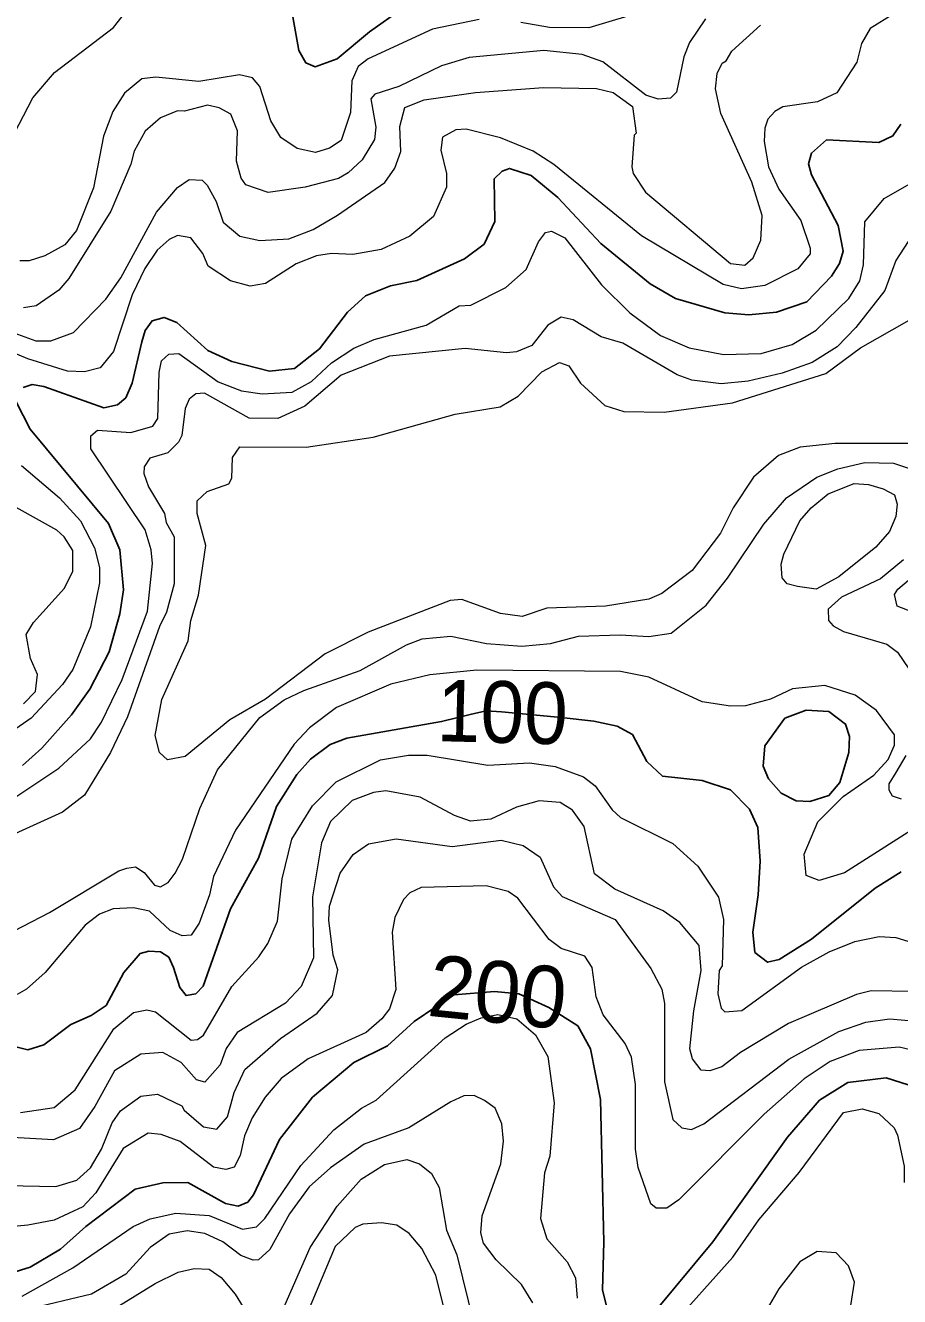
# Model space of a CAD drawing. Extents: x 673.6 to 698.9, y 7012 to 7040.1.
# Drawn here: x 696.817 to 697.951, y 7014.545 to 7016.194 of the extents above; entities that cross this region are included whole.
import ezdxf
from ezdxf.enums import TextEntityAlignment as Align

# ---------------------------------------------------------------- set-up
doc = ezdxf.new("R2010")
doc.units = 0
doc.header["$LTSCALE"] = 0.032
doc.layers.add('1', color=7, linetype='Continuous', lineweight=25)
doc.layers.add('2', color=7, linetype='Continuous', lineweight=13)
doc.layers.add('61', color=7, linetype='Continuous')

msp = doc.modelspace()

# ---------------------------------------------------------------- linework, layer by layer
at = {"layer": '1'}
for points in [[(697.3059, 7016.2157), (697.2629, 7016.1858), (697.2209, 7016.1507), (697.1924, 7016.1402), (697.1805, 7016.1453), (697.1715, 7016.1616), (697.1635, 7016.2053)], [(697.9522, 7016.0661), (697.9418, 7016.0508), (697.9237, 7016.0421), (697.8556, 7016.0454), (697.8364, 7016.0283), (697.8324, 7016.0145), (697.8361, 7016), (697.8709, 7015.9345), (697.8773, 7015.9013), (697.8725, 7015.8852), (697.8624, 7015.8686), (697.8301, 7015.8353), (697.7908, 7015.822), (697.7552, 7015.8187), (697.7238, 7015.8213), (697.6597, 7015.8397), (697.6272, 7015.8587), (697.5629, 7015.9113), (697.5073, 7015.971), (697.4729, 7015.9994), (697.4445, 7016.0085), (697.4352, 7016.005), (697.4248, 7015.9952), (697.4255, 7015.9397), (697.4117, 7015.9102), (697.3864, 7015.8912), (697.3244, 7015.8633), (697.2904, 7015.8563), (697.2577, 7015.8431), (697.2343, 7015.8222), (697.1981, 7015.7746), (697.1657, 7015.7489), (697.1332, 7015.7457), (697.0845, 7015.7581), (697.0533, 7015.7723), (697.0132, 7015.8085), (696.9966, 7015.8152), (696.9811, 7015.8108), (696.9721, 7015.7982), (696.9677, 7015.7838), (696.9551, 7015.7299), (696.9471, 7015.711), (696.9362, 7015.7018), (696.9184, 7015.6979), (696.8405, 7015.7258), (696.8254, 7015.7282), (696.8137, 7015.7245)], [(696.8045, 7015.7058), (696.8229, 7015.6703), (696.9244, 7015.548), (696.939, 7015.5138), (696.9439, 7015.462), (696.9392, 7015.4308), (696.9255, 7015.3815), (696.9004, 7015.333), (696.8765, 7015.2997), (696.8382, 7015.2568), (696.813, 7015.2342)], [(696.7763, 7014.8761), (696.8198, 7014.8656), (696.8408, 7014.872), (696.8756, 7014.8981), (696.902, 7014.9099), (696.9214, 7014.9228), (696.9445, 7014.9656), (696.9654, 7014.9902), (696.9766, 7014.9932), (696.9919, 7014.9925), (697.0027, 7014.9858), (697.0088, 7014.9722), (697.017, 7014.9464), (697.025, 7014.9359), (697.0377, 7014.9381), (697.0473, 7014.9478), (697.0827, 7015.0484), (697.1189, 7015.1141), (697.1425, 7015.181), (697.1689, 7015.2226), (697.1864, 7015.2426), (697.2119, 7015.2615), (697.2336, 7015.2698), (697.3565, 7015.2912), (697.3937, 7015.3002), (697.4144, 7015.3049), (697.4344, 7015.3036), (697.5114, 7015.2963), (697.5539, 7015.2916), (697.5844, 7015.2852), (697.604, 7015.2743), (697.6228, 7015.2394), (697.643, 7015.2205), (697.6946, 7015.2147), (697.7314, 7015.2028), (697.7558, 7015.1777), (697.7668, 7015.1538), (697.7698, 7015.1102), (697.7673, 7015.0663), (697.7602, 7015.0179), (697.7627, 7014.9918), (697.7793, 7014.979), (697.7944, 7014.9826), (697.8361, 7015.009), (697.9189, 7015.0749), (697.9527, 7015.0961)], [(697.5727, 7014.5245), (697.5654, 7014.5542), (697.5669, 7014.6161), (697.5627, 7014.8009), (697.5495, 7014.8666), (697.5331, 7014.8966), (697.4956, 7014.9202), (697.4569, 7014.9381), (697.4253, 7014.9409), (697.3727, 7014.9366), (697.3489, 7014.921), (697.3209, 7014.9024), (697.2863, 7014.8706), (697.2428, 7014.8488), (697.1891, 7014.804), (697.1464, 7014.7491), (697.1126, 7014.6776), (697.1051, 7014.6679), (697.0927, 7014.6626), (697.0763, 7014.6663), (697.0273, 7014.6936), (696.9949, 7014.6928), (696.9591, 7014.6847), (696.8949, 7014.6364), (696.862, 7014.6068), (696.8227, 7014.5837), (696.7792, 7014.5704)], [(698.0445, 7014.4841), (698.0566, 7014.549), (698.055, 7014.5816), (698.0436, 7014.6145), (698.0207, 7014.6633), (697.9826, 7014.7939), (697.9619, 7014.8202), (697.9333, 7014.8293), (697.8833, 7014.8232), (697.8468, 7014.8001), (697.8051, 7014.752), (697.7085, 7014.6165), (697.6361, 7014.5296)]]:
    msp.add_lwpolyline(points, dxfattribs=at)
msp.add_lwpolyline([(697.8019, 7015.2957), (697.8295, 7015.3058), (697.8589, 7015.304), (697.8806, 7015.2878), (697.8857, 7015.2718), (697.8849, 7015.2512), (697.8732, 7015.2121), (697.8589, 7015.1953), (697.8342, 7015.1873), (697.8165, 7015.1883), (697.797, 7015.1983), (697.7804, 7015.2167), (697.7738, 7015.2331), (697.7756, 7015.2595)], close=True, dxfattribs=at)
at = {"layer": '2'}
for points in [[(696.7967, 7016.0427), (696.8264, 7016.1), (696.8546, 7016.1327), (696.9311, 7016.1912), (696.9536, 7016.2198)], [(697.9432, 7016.209), (697.9126, 7016.19), (697.9012, 7016.1707), (697.8953, 7016.1462), (697.8691, 7016.1064), (697.844, 7016.095), (697.7993, 7016.0884), (697.7888, 7016.0824), (697.7798, 7016.0723), (697.7756, 7016.0606), (697.7748, 7016.0435), (697.7806, 7016.0105), (697.7938, 7015.9818), (697.8225, 7015.941), (697.8347, 7015.9049), (697.8344, 7015.8979), (697.8185, 7015.8783), (697.7759, 7015.8565), (697.7457, 7015.8524), (697.7218, 7015.858), (697.6156, 7015.9212), (697.5019, 7016.0134), (697.4753, 7016.0309), (697.4331, 7016.0481), (697.3885, 7016.0593), (697.3751, 7016.0587), (697.3578, 7016.0489), (697.3557, 7016.0323), (697.363, 7016.0019), (697.363, 7015.9842), (697.346, 7015.9463), (697.3153, 7015.9206), (697.2781, 7015.9032), (697.2414, 7015.8968), (697.2135, 7015.8983), (697.1942, 7015.8952), (697.1678, 7015.8846), (697.1283, 7015.8591), (697.1082, 7015.8556), (697.0827, 7015.8628), (697.0539, 7015.8818), (697.0469, 7015.8981), (697.0311, 7015.9187), (697.0139, 7015.9214), (697.0033, 7015.9164), (696.9874, 7015.9024), (696.9714, 7015.8785), (696.955, 7015.8447), (696.9311, 7015.7709), (696.9135, 7015.7499), (696.8935, 7015.7446), (696.8712, 7015.7457), (696.8197, 7015.7617), (696.7714, 7015.7817)], [(697.4051, 7016.2016), (697.3449, 7016.1892), (697.2612, 7016.1506), (697.2482, 7016.1407), (697.2399, 7016.1223), (697.2383, 7016.081), (697.2261, 7016.0446), (697.2109, 7016.0349), (697.1929, 7016.0292), (697.1693, 7016.0343), (697.1482, 7016.0485), (697.1349, 7016.0704), (697.1209, 7016.1146), (697.1111, 7016.126), (697.0944, 7016.13), (697.0417, 7016.1211), (696.9858, 7016.1268), (696.9679, 7016.1247), (696.9452, 7016.1061), (696.93, 7016.0823), (696.9178, 7016.0504), (696.9052, 7015.9835), (696.8831, 7015.9279), (696.8678, 7015.9093), (696.8417, 7015.895), (696.8214, 7015.8887), (696.8093, 7015.8886)], [(697.6987, 7016.2027), (697.6779, 7016.1718), (697.6705, 7016.1531), (697.6612, 7016.1072), (697.6532, 7016.0996), (697.6373, 7016.0981), (697.6213, 7016.1034), (697.5657, 7016.1467), (697.5389, 7016.1564), (697.4892, 7016.1614), (697.3923, 7016.1522), (697.3562, 7016.1415), (697.3009, 7016.1147), (697.2697, 7016.1047), (697.2646, 7016.0986), (697.271, 7016.0618), (697.2694, 7016.046), (697.2534, 7016.0197), (697.2354, 7016.0026), (697.2228, 7015.9955), (697.1797, 7015.984), (697.1316, 7015.9773), (697.1027, 7015.9874), (697.0965, 7015.996), (697.0906, 7016.0178), (697.0918, 7016.0574), (697.083, 7016.0788), (697.0679, 7016.087), (697.0528, 7016.0906), (697.023, 7016.0826), (697.0138, 7016.0832), (696.9917, 7016.0742), (696.9721, 7016.0567), (696.9577, 7016.0309), (696.9534, 7016.0139), (696.9277, 7015.9529), (696.8729, 7015.8657), (696.8602, 7015.8507), (696.8308, 7015.8304), (696.8144, 7015.8278)], [(697.6241, 7016.2138), (697.5475, 7016.191), (697.4963, 7016.1913), (697.4593, 7016.1976)], [(697.5574, 7016.112), (697.579, 7016.1068), (697.6041, 7016.0887), (697.6088, 7016.0542), (697.6064, 7016.0516), (697.6031, 7016.0106), (697.6049, 7016.0017), (697.6212, 7015.9775), (697.7314, 7015.8854), (697.7499, 7015.8832), (697.7605, 7015.8924), (697.7707, 7015.9156), (697.7723, 7015.9474), (697.759, 7015.9907), (697.7187, 7016.0798), (697.7116, 7016.1117), (697.7139, 7016.1314), (697.7203, 7016.1452), (697.7257, 7016.1479), (697.7329, 7016.1605), (697.7702, 7016.1942)], [(697.3024, 7016.0628), (697.309, 7016.0877), (697.3339, 7016.0973), (697.4005, 7016.1071), (697.4889, 7016.1136), (697.5574, 7016.112)], [(696.7923, 7015.7988), (696.8301, 7015.7847), (696.8496, 7015.7851), (696.879, 7015.7958), (696.9211, 7015.839), (696.9405, 7015.8668), (696.9868, 7015.9516), (697.0138, 7015.9838), (697.0292, 7015.9943), (697.0461, 7015.9933), (697.0526, 7015.9866), (697.0639, 7015.9657), (697.0734, 7015.9389), (697.0948, 7015.9206), (697.1207, 7015.9149), (697.1585, 7015.917), (697.1898, 7015.9293), (697.2217, 7015.9477), (697.283, 7015.9901), (697.2959, 7016.0089), (697.3036, 7016.0303), (697.3024, 7016.0628)], [(697.5163, 7015.9184), (697.5641, 7015.8577), (697.6005, 7015.8211), (697.6405, 7015.7917), (697.6777, 7015.7757), (697.7221, 7015.767), (697.7709, 7015.7686), (697.8112, 7015.7802), (697.8423, 7015.7986), (697.8846, 7015.8398), (697.899, 7015.8626), (697.9037, 7015.8836), (697.9055, 7015.9391), (697.9307, 7015.9694), (697.969, 7015.9916)], [(697.4397, 7015.8542), (697.4662, 7015.8773), (697.4824, 7015.9134), (697.4913, 7015.9254), (697.499, 7015.9272), (697.5163, 7015.9184)], [(697.9619, 7015.9138), (697.9456, 7015.889), (697.9313, 7015.8501), (697.8939, 7015.8021), (697.8698, 7015.7772), (697.837, 7015.7566), (697.7983, 7015.743), (697.7542, 7015.7325), (697.7191, 7015.7291), (697.6809, 7015.7339), (697.6619, 7015.7408), (697.5915, 7015.7817), (697.5635, 7015.7899), (697.5273, 7015.812), (697.5117, 7015.8155), (697.4943, 7015.8053), (697.4734, 7015.7787), (697.4536, 7015.7706), (697.4408, 7015.7694), (697.387, 7015.7751), (697.2888, 7015.7651), (697.2263, 7015.7404), (697.179, 7015.7002), (697.144, 7015.6841), (697.1071, 7015.6848), (697.0488, 7015.717), (697.0377, 7015.7163), (697.0292, 7015.7092), (697.0239, 7015.697), (697.0195, 7015.6621), (697.0154, 7015.6535), (697.0014, 7015.6396), (696.9779, 7015.6328), (696.9706, 7015.6217), (696.9703, 7015.6128), (696.9763, 7015.5957), (696.9972, 7015.5612), (696.9994, 7015.5495), (697.0097, 7015.5307), (697.0098, 7015.4698), (696.9997, 7015.4329), (696.9906, 7015.4145), (696.9491, 7015.2971), (696.9269, 7015.2511), (696.8935, 7015.1955), (696.8648, 7015.1735), (696.798, 7015.1434)], [(696.774, 7015.1737), (696.8599, 7015.2308), (696.901, 7015.2687), (696.9152, 7015.2903), (696.942, 7015.3456), (696.9751, 7015.4344), (696.9817, 7015.4961), (696.98, 7015.514), (696.972, 7015.5398), (696.9016, 7015.6449), (696.9014, 7015.6616), (696.9102, 7015.6692), (696.9533, 7015.6659), (696.9818, 7015.6744), (696.9883, 7015.6843), (696.9901, 7015.7439), (696.9933, 7015.7591), (697.0028, 7015.7675), (697.0156, 7015.7684), (697.0666, 7015.7319), (697.0968, 7015.7201), (697.1236, 7015.716), (697.1627, 7015.7185), (697.1877, 7015.7322), (697.2135, 7015.7562), (697.2425, 7015.7756), (697.2691, 7015.7865), (697.3367, 7015.8053), (697.3793, 7015.8302), (697.3943, 7015.8311), (697.4397, 7015.8542)], [(697.2677, 7015.6601), (697.374, 7015.6899), (697.4326, 7015.6992), (697.4559, 7015.7133), (697.4866, 7015.7449), (697.5093, 7015.757), (697.5217, 7015.7526), (697.5365, 7015.7301), (697.5683, 7015.7009), (697.5931, 7015.6933), (697.6452, 7015.6922), (697.7338, 7015.7044), (697.855, 7015.7425), (697.8997, 7015.7759), (697.9629, 7015.8119)], [(697.0804, 7015.5996), (697.0845, 7015.6066), (697.0854, 7015.6335), (697.0946, 7015.6476), (697.1809, 7015.647), (697.2677, 7015.6601)], [(697.9852, 7015.6519), (697.8672, 7015.6518), (697.8216, 7015.6469), (697.7937, 7015.6362), (697.7612, 7015.608), (697.7347, 7015.5684), (697.7182, 7015.5354), (697.6816, 7015.4872), (697.6422, 7015.4574), (697.6251, 7015.45), (697.569, 7015.441), (697.4932, 7015.4382), (697.4611, 7015.4276), (697.4327, 7015.4315), (697.3829, 7015.4493), (697.3677, 7015.448), (697.2614, 7015.4071), (697.2053, 7015.379), (697.1279, 7015.3204), (697.0818, 7015.2933), (697.0241, 7015.2458), (697.0009, 7015.2415), (696.9908, 7015.2512), (696.985, 7015.2733), (696.9938, 7015.3198), (697.0279, 7015.3957), (697.0312, 7015.4224), (697.041, 7015.455), (697.0508, 7015.5197), (697.0395, 7015.5608), (697.0394, 7015.5776), (697.0526, 7015.5895), (697.0804, 7015.5996)], [(696.7783, 7015.0078), (696.8481, 7015.0436), (696.938, 7015.0977), (696.9483, 7015.1012), (696.9595, 7015.1027), (696.9706, 7015.0952), (696.984, 7015.0788), (696.992, 7015.0767), (697.0019, 7015.0826), (697.0108, 7015.0947), (697.0204, 7015.1128), (697.0431, 7015.1785), (697.0657, 7015.2286), (697.1209, 7015.2963), (697.1521, 7015.3192), (697.178, 7015.3316), (697.2507, 7015.3573), (697.3112, 7015.3908), (697.3315, 7015.3986), (697.3684, 7015.402), (697.4149, 7015.3922), (697.4607, 7015.389), (697.4978, 7015.3922), (697.5341, 7015.4019), (697.5882, 7015.4036), (697.6251, 7015.4013), (697.6541, 7015.4059), (697.6998, 7015.4421), (697.7275, 7015.477), (697.7745, 7015.5472), (697.8038, 7015.5815), (697.8431, 7015.6081), (697.8706, 7015.6188), (697.9055, 7015.6272), (697.9425, 7015.6264), (697.9635, 7015.6195)], [(696.8115, 7015.6231), (696.8609, 7015.5811), (696.888, 7015.5516), (696.9064, 7015.5165), (696.9127, 7015.4908), (696.9127, 7015.471), (696.9013, 7015.4139), (696.8784, 7015.3587), (696.8648, 7015.3394), (696.8243, 7015.2955), (696.7783, 7015.2642)], [(696.8141, 7015.3143), (696.8297, 7015.33), (696.8322, 7015.3524), (696.8235, 7015.3729), (696.8176, 7015.404), (696.827, 7015.4198), (696.8674, 7015.4643), (696.8782, 7015.4862), (696.8781, 7015.5128), (696.8669, 7015.5308), (696.8573, 7015.5395), (696.7817, 7015.5811)], [(697.9558, 7015.5009), (697.9259, 7015.4761), (697.8752, 7015.4526), (697.8578, 7015.4369), (697.8585, 7015.4224), (697.8646, 7015.4151), (697.878, 7015.4079), (697.934, 7015.3917), (697.9477, 7015.381), (697.9698, 7015.3488)], [(698.0157, 7015.4146), (697.9474, 7015.4408), (697.9441, 7015.456), (697.9482, 7015.4629), (697.9898, 7015.498)], [(697.9897, 7015.1655), (697.8791, 7015.0948), (697.8463, 7015.0849), (697.8295, 7015.0916), (697.8266, 7015.1193), (697.8444, 7015.1613), (697.8774, 7015.1941), (697.9172, 7015.2215), (697.9357, 7015.2419), (697.9439, 7015.2605), (697.9441, 7015.2739), (697.9204, 7015.3057), (697.8931, 7015.3256), (697.8536, 7015.3378), (697.8118, 7015.3338), (697.783, 7015.3202), (697.7506, 7015.3116), (697.7314, 7015.3112), (697.6944, 7015.3168), (697.6251, 7015.3486), (697.5886, 7015.356), (697.4022, 7015.3576), (697.3414, 7015.3519), (697.2905, 7015.3398), (697.2201, 7015.3092), (697.185, 7015.2832), (697.1653, 7015.2618), (697.0893, 7015.1503), (697.0608, 7015.0902), (697.0556, 7015.0664), (697.042, 7015.0297), (697.0317, 7015.0142), (697.0201, 7015.0132), (697.0045, 7015.0203), (696.9775, 7015.0454), (696.9571, 7015.0495), (696.9305, 7015.0481), (696.9128, 7015.0412), (696.8944, 7015.0271), (696.8423, 7014.9659), (696.818, 7014.9439), (696.8062, 7014.9371)], [(697.2199, 7015.2131), (697.2773, 7015.2417), (697.3134, 7015.2475), (697.338, 7015.2475), (697.4166, 7015.2345), (697.4706, 7015.2376)], [(697.9587, 7015.2472), (697.9458, 7015.225), (697.9364, 7015.2106), (697.9364, 7015.2025), (697.9408, 7015.195), (697.9528, 7015.1909)], [(697.4706, 7015.2376), (697.5038, 7015.2329), (697.5405, 7015.2196), (697.5556, 7015.2079), (697.5779, 7015.1766), (697.5885, 7015.1668), (697.6566, 7015.1329), (697.6889, 7015.1037), (697.7157, 7015.0633), (697.722, 7015.0346), (697.7206, 7014.9743), (697.7165, 7014.9683), (697.7148, 7014.9382), (697.7193, 7014.9196), (697.7241, 7014.9148), (697.7458, 7014.9165), (697.8234, 7014.9727), (697.8591, 7014.9927), (697.8923, 7015.0059), (697.924, 7015.0126), (697.9459, 7015.0111), (697.9837, 7014.9993)], [(696.8103, 7014.7841), (696.8538, 7014.7908), (696.8812, 7014.8134), (696.9312, 7014.8927), (696.957, 7014.9138), (696.9743, 7014.9173), (696.9855, 7014.9147), (697.0315, 7014.8778), (697.0398, 7014.879), (697.0475, 7014.8843), (697.0845, 7014.9476), (697.1196, 7014.986), (697.1313, 7015.0035), (697.1436, 7015.0323), (697.1496, 7015.0872), (697.1623, 7015.1385), (697.1892, 7015.182), (697.2199, 7015.2131)], [(697.9679, 7014.941), (697.9137, 7014.9418), (697.8946, 7014.9371), (697.8066, 7014.8998), (697.7442, 7014.8619), (697.72, 7014.8435), (697.7045, 7014.8384), (697.6933, 7014.839), (697.6821, 7014.8538), (697.6787, 7014.8667), (697.6837, 7014.9162), (697.6934, 7014.9682), (697.6908, 7015.0009), (697.6654, 7015.0306), (697.6437, 7015.0456), (697.581, 7015.0736), (697.5548, 7015.0939), (697.5415, 7015.1552), (697.5262, 7015.1764), (697.5102, 7015.1861), (697.4831, 7015.1883), (697.4537, 7015.1802), (697.4202, 7015.1645), (697.3941, 7015.1622), (697.3733, 7015.1693), (697.3288, 7015.1932), (697.2842, 7015.2015), (697.268, 7015.1991), (697.2404, 7015.1887), (697.2125, 7015.1614), (697.2009, 7015.1341), (697.1889, 7015.0638), (697.1905, 7014.9846), (697.1742, 7014.9475), (697.1541, 7014.9259), (697.0913, 7014.8879), (697.0769, 7014.8672), (697.0694, 7014.8459), (697.0495, 7014.8236), (697.0384, 7014.8265), (697.0187, 7014.8489), (696.995, 7014.8621), (696.9662, 7014.8598), (696.9323, 7014.8381), (696.9068, 7014.792), (696.8868, 7014.7635), (696.8533, 7014.7487), (696.7842, 7014.7528)], [(696.7924, 7014.6895), (696.8563, 7014.688), (696.8832, 7014.6964), (696.9011, 7014.7125), (696.9152, 7014.7365), (696.9291, 7014.7709), (696.9399, 7014.7865), (696.9662, 7014.8054), (696.988, 7014.8079), (697.0194, 7014.7929), (697.0224, 7014.7872), (697.0478, 7014.7656), (697.0648, 7014.7625), (697.0787, 7014.7787), (697.0875, 7014.8103), (697.1012, 7014.84), (697.1475, 7014.88), (697.195, 7014.9129), (697.2152, 7014.9357), (697.2218, 7014.969), (697.2159, 7014.9883), (697.2103, 7015.0336), (697.211, 7015.0517), (697.2251, 7015.0947), (697.2417, 7015.1188), (697.2618, 7015.1328), (697.2977, 7015.1389), (697.3702, 7015.1293), (697.4337, 7015.1374), (697.4622, 7015.1305), (697.4844, 7015.1152), (697.5018, 7015.077), (697.513, 7015.0642), (697.5818, 7015.0344), (697.6278, 7014.9711), (697.6421, 7014.9441), (697.6457, 7014.9254), (697.6458, 7014.8239), (697.6565, 7014.7752), (697.6682, 7014.7643), (697.6807, 7014.7621), (697.6965, 7014.7695)], [(697.9721, 7014.8639), (697.9498, 7014.8687), (697.898, 7014.8644), (697.8607, 7014.8504), (697.8268, 7014.8278), (697.775, 7014.7819), (697.6641, 7014.6709), (697.6486, 7014.66), (697.635, 7014.6601), (697.6278, 7014.6658), (697.6114, 7014.7127), (697.608, 7014.7365), (697.6079, 7014.8206), (697.603, 7014.8561), (697.5944, 7014.8738), (697.566, 7014.9108), (697.557, 7014.934), (697.5516, 7014.9722), (697.5422, 7014.9868), (697.5115, 7014.997), (697.4959, 7015.0087), (697.4552, 7015.0623), (697.4427, 7015.0707), (697.4144, 7015.0781), (697.3299, 7015.0759), (697.3155, 7015.0692), (697.3072, 7015.0603), (697.2959, 7015.0369), (697.2925, 7015.0182), (697.2973, 7014.9436), (697.2889, 7014.9185), (697.279, 7014.9055), (697.2588, 7014.888), (697.1836, 7014.8537), (697.1483, 7014.8282), (697.1275, 7014.8041), (697.1107, 7014.7772), (697.1007, 7014.7538), (697.0951, 7014.7283), (697.0873, 7014.7133), (697.0767, 7014.7102), (697.0607, 7014.7131), (697.0176, 7014.7464), (696.9928, 7014.7558), (696.9757, 7014.7575), (696.9434, 7014.7374), (696.9082, 7014.6801), (696.8913, 7014.6618), (696.8538, 7014.6444), (696.8198, 7014.6379), (696.757, 7014.6318)], [(696.8125, 7014.5458), (696.8782, 7014.5827), (696.9565, 7014.6365), (696.9784, 7014.6463), (697.0117, 7014.6535), (697.0549, 7014.6507), (697.0981, 7014.633), (697.1163, 7014.636), (697.1271, 7014.6468), (697.1738, 7014.7155), (697.2167, 7014.7619), (697.2527, 7014.7896), (697.2716, 7014.8003), (697.3612, 7014.8808), (697.3884, 7014.8986), (697.4077, 7014.9068), (697.4296, 7014.9112), (697.4542, 7014.9058), (697.4784, 7014.8848), (697.4944, 7014.8566), (697.5027, 7014.7965), (697.497, 7014.7277), (697.4898, 7014.7059), (697.4847, 7014.6469), (697.4928, 7014.6205), (697.5196, 7014.5907), (697.5304, 7014.5696), (697.5324, 7014.5436)], [(697.6965, 7014.7695), (697.807, 7014.8533), (697.8718, 7014.8892), (697.9066, 7014.9015), (697.9375, 7014.9057), (697.9626, 7014.9033)], [(697.4747, 7014.5372), (697.4603, 7014.5609), (697.4274, 7014.5933), (697.411, 7014.6145), (697.4074, 7014.6282), (697.4092, 7014.6501), (697.4335, 7014.7176), (697.437, 7014.7471), (697.4345, 7014.7695), (697.4262, 7014.7898), (697.412, 7014.7997), (697.3988, 7014.8063), (697.3854, 7014.8056), (697.3684, 7014.7982), (697.3141, 7014.7645), (697.2562, 7014.743), (697.2124, 7014.7122), (697.1847, 7014.6877), (697.1594, 7014.6529), (697.1338, 7014.6067), (697.1189, 7014.5932), (697.112, 7014.5927), (697.096, 7014.5988), (697.0727, 7014.6166), (697.0496, 7014.6272), (697.0267, 7014.6305), (697.003, 7014.6266), (696.9786, 7014.609), (696.9469, 7014.5743), (696.9023, 7014.5487), (696.819, 7014.5285)], [(697.6498, 7014.5024), (697.7341, 7014.5964), (697.7678, 7014.645), (697.8203, 7014.7063), (697.8778, 7014.7841), (697.9021, 7014.789), (697.9238, 7014.783), (697.9435, 7014.7641), (697.948, 7014.7549), (697.9564, 7014.7147), (697.9564, 7014.6932)], [(697.1504, 7014.5281), (697.1861, 7014.6093), (697.2212, 7014.6627), (697.2521, 7014.6977), (697.2825, 7014.7167), (697.3114, 7014.7231), (697.3278, 7014.7178), (697.3435, 7014.7049), (697.3532, 7014.6871), (697.363, 7014.6316), (697.3763, 7014.5998), (697.3984, 7014.51)], [(697.3604, 7014.528), (697.3492, 7014.5734), (697.331, 7014.6077), (697.3145, 7014.6271), (697.2986, 7014.6382), (697.2784, 7014.6411), (697.2543, 7014.6393), (697.2443, 7014.6349), (697.2184, 7014.6102), (697.1412, 7014.4259)], [(697.8873, 7014.5338), (697.8921, 7014.5641), (697.8845, 7014.5855), (697.8684, 7014.6023), (697.8437, 7014.6041), (697.8211, 7014.5903), (697.794, 7014.5557), (697.7729, 7014.5193)], [(696.9126, 7014.5178), (696.985, 7014.5622), (697.015, 7014.5771), (697.0354, 7014.5818), (697.055, 7014.5812), (697.0708, 7014.5702), (697.0888, 7014.5487), (697.1187, 7014.5)]]:
    msp.add_lwpolyline(points, dxfattribs=at)
msp.add_lwpolyline([(697.8579, 7015.5866), (697.8916, 7015.6), (697.9104, 7015.5986), (697.9294, 7015.593), (697.9439, 7015.5852), (697.9476, 7015.5733), (697.9458, 7015.557), (697.9374, 7015.5377), (697.9197, 7015.5174), (697.8716, 7015.4789), (697.8423, 7015.463), (697.8183, 7015.4662), (697.8046, 7015.4698), (697.7984, 7015.4774), (697.797, 7015.4953), (697.8003, 7015.5084), (697.8213, 7015.5513), (697.8359, 7015.5684)], close=True, dxfattribs=at)

# ---------------------------------------------------------------- texts
at = {"layer": '61', "width": 0.95}
msp.add_text('100', height=0.08, rotation=358.499, dxfattribs=at).set_placement((697.4343, 7015.2636), align=Align.CENTER)
at = {"layer": '61'}
msp.add_text('200', height=0.08, rotation=354.205, dxfattribs=at).set_placement((697.4253, 7014.9008), align=Align.CENTER)

doc.saveas('drawing.dxf')
